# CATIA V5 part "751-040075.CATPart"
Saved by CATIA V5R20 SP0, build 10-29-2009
Part number: 751-040075
Source: Unknown
Property "A": "45.000"
Property "ARTICLENO": "751-040075"
Property "BOMINFO": "751-040075"
Property "CODE": "751-040075"
Property "D1": "45.000"
Property "D2": "40.000"
Property "D3": "44.000"
Property "D4": "36.000"
Property "L": "75.000"
Property "L1": "55.000"
Property "LINA": "751-040075"
Property "MAXFORCE": "9800 N"
Property "NB": "751-040075"
Property "NBSYN": "$CODE."
Property "NN": "751"
Property "NT": "Slide Stop Block"
Property "SUPPLIER": "CF"
Property "W": "70.000"
Bounding box of the stored display mesh (mm): x 0 to 45, y 0 to 70, z -37.5 to 37.5
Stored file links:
  C:\Users\Utente\Desktop\3D files 751\751-040075.CATPart
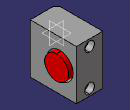
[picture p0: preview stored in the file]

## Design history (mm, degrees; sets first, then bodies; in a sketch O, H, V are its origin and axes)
Body1 "Geometry.1" (main body)
  Solid1 "751-040075.catpart": solid without history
